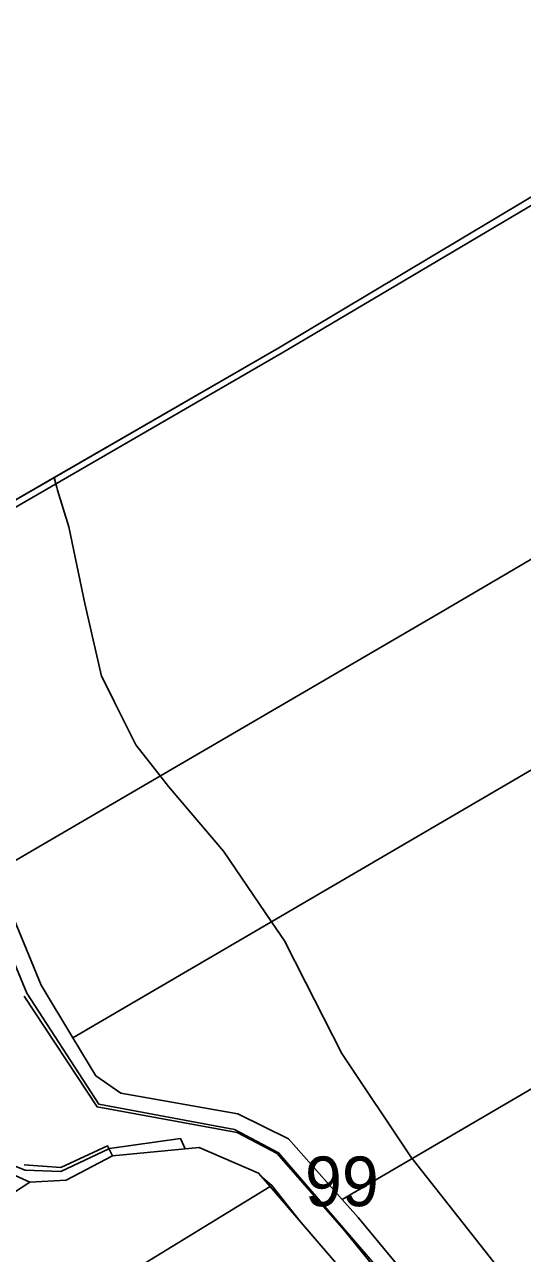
# Model space of a CAD drawing. Extents: x -522079 to -518792, y -1142400 to -1139961.
# Drawn here: x -520688.5 to -520538, y -1140520.9 to -1140149.5 of the extents above; entities that cross this region are included whole.
import ezdxf

# ---------------------------------------------------------------- set-up
doc = ezdxf.new("R2010")
doc.units = 0
for name, color, linetype in [('Hranice parcel', 7, 'Continuous'), ('Parcelní čísla', 7, 'Continuous'), ('Poz předměty', 7, 'Continuous'), ('Vnitřní kresba', 7, 'Continuous'), ('Značky bodu BP', 7, 'Continuous')]:
    doc.layers.add(name, color=color, linetype=linetype)

msp = doc.modelspace()

# ---------------------------------------------------------------- linework, layer by layer
at = {"layer": 'Hranice parcel'}
for points in [[(-520489.41, -1140176.97), (-520610.57, -1140248.68), (-520727.12, -1140316.09), (-520736.79, -1140321.94), (-520738.8, -1140318.04), (-520737.2, -1140317.47), (-520736.37, -1140319.22), (-520728.21, -1140314.51), (-520611.62, -1140247.2), (-520491.09, -1140175.17)], [(-520560.63, -1140549.81), (-520611.7, -1140490.5), (-520625.05, -1140483.49), (-520666, -1140475.86), (-520687.78, -1140442.24), (-520709.46, -1140390.03), (-520724.04, -1140346.68), (-520736.79, -1140321.94), (-520727.12, -1140316.09), (-520729.96, -1140323.84), (-520719.64, -1140344.89), (-520704.93, -1140387.92), (-520697.54, -1140405.82), (-520683.48, -1140439.85), (-520673.87, -1140455.8), (-520666.98, -1140467.24), (-520659.41, -1140472.47), (-520623.97, -1140478.75), (-520608.7, -1140486.32), (-520592.52, -1140504.62), (-520587.65, -1140510.13), (-520562.49, -1140540.48)]]:
    msp.add_lwpolyline(points, dxfattribs=at)
at = {"layer": 'Parcelní čísla'}
for points in [[(-520697.54, -1140405.82), (-520704.93, -1140387.92), (-520719.64, -1140344.89), (-520729.96, -1140323.84), (-520727.12, -1140316.09), (-520610.57, -1140248.68), (-520489.41, -1140176.97), (-520443.64, -1140149.48), (-520437.53, -1140151.12), (-520407.86, -1140236.34), (-520563.45, -1140327.62)], [(-520407.86, -1140236.34), (-520389.24, -1140289.48), (-520535.21, -1140374.77), (-520673.87, -1140455.8), (-520683.48, -1140439.85), (-520697.54, -1140405.82), (-520563.45, -1140327.62)], [(-520592.52, -1140504.62), (-520608.7, -1140486.32), (-520623.97, -1140478.75), (-520659.41, -1140472.47), (-520666.98, -1140467.24), (-520673.87, -1140455.8), (-520535.21, -1140374.77), (-520389.24, -1140289.48), (-520361.23, -1140369.4)], [(-520361.23, -1140369.4), (-520345.47, -1140414.38), (-520469.06, -1140486.19), (-520562.49, -1140540.48), (-520587.65, -1140510.13), (-520592.52, -1140504.62)]]:
    msp.add_lwpolyline(points, close=True, dxfattribs=at)
at = {"layer": 'Poz předměty'}
for points in [[(-520732.54, -1140476.21), (-520724, -1140470.78), (-520714.97, -1140487.48), (-520699.14, -1140493.81), (-520686.89, -1140499.45), (-520708.82, -1140513.67)], [(-520686.89, -1140499.45), (-520675.92, -1140498.77), (-520661.91, -1140491.42), (-520635.69, -1140488.94), (-520617.72, -1140496.63), (-520614.24, -1140500.69), (-520688.32, -1140546.05), (-520708.82, -1140513.67)], [(-520688.32, -1140546.05), (-520614.24, -1140500.69), (-520587.68, -1140531.64), (-520567.56, -1140556.74), (-520562.84, -1140560.36), (-520646.64, -1140611.87)]]:
    msp.add_lwpolyline(points, close=True, dxfattribs=at)
at = {"layer": 'Vnitřní kresba'}
for points in [[(-520709.46, -1140390.03), (-520687.78, -1140442.24), (-520666, -1140475.86), (-520625.05, -1140483.49), (-520611.7, -1140490.5), (-520560.63, -1140549.81)], [(-520688.63, -1140494.17), (-520677.55, -1140494.96), (-520663.43, -1140488.4), (-520661.91, -1140491.42), (-520675.92, -1140498.77), (-520686.89, -1140499.45), (-520699.14, -1140493.81)], [(-520587.68, -1140531.64), (-520614.24, -1140500.69), (-520617.72, -1140496.63), (-520635.69, -1140488.94), (-520661.91, -1140491.42), (-520663.43, -1140488.4), (-520677.55, -1140494.96), (-520688.63, -1140494.17)]]:
    msp.add_lwpolyline(points, dxfattribs=at)
at = {"layer": 'Značky bodu BP'}
for points in [[(-520542.49, -1140528.86), (-520571.02, -1140492.64), (-520571.34, -1140492.23), (-520571.5, -1140492.02), (-520592.55, -1140460.53), (-520603.54, -1140438.95), (-520609.92, -1140426.44), (-520613.83, -1140420.71), (-520628.38, -1140399.39), (-520645.01, -1140379.75), (-520647.47, -1140376.62), (-520654.86, -1140367.24), (-520661.31, -1140354.3), (-520663.36, -1140350.18), (-520665.2, -1140346.48), (-520670.25, -1140324.52), (-520675.06, -1140301.35), (-520678.51, -1140290.17), (-520678.74, -1140289.42), (-520679.03, -1140288.27), (-520679.51, -1140286.39), (-520611.62, -1140247.2), (-520491.09, -1140175.17)], [(-520728.21, -1140314.51), (-520679.51, -1140286.39), (-520679.03, -1140288.27), (-520678.74, -1140289.42), (-520678.51, -1140290.17), (-520675.06, -1140301.35), (-520670.25, -1140324.52), (-520665.2, -1140346.48), (-520663.36, -1140350.18), (-520661.31, -1140354.3), (-520654.86, -1140367.24), (-520647.47, -1140376.62), (-520645.01, -1140379.75), (-520628.38, -1140399.39), (-520613.83, -1140420.71), (-520609.92, -1140426.44), (-520603.54, -1140438.95), (-520592.55, -1140460.53), (-520571.5, -1140492.02), (-520571.34, -1140492.23), (-520571.02, -1140492.64), (-520542.49, -1140528.86)], [(-520562.29, -1140550.47), (-520591.73, -1140514.02), (-520612.12, -1140490.78), (-520624.22, -1140484.36), (-520666.58, -1140476.66), (-520688.6, -1140443.21)], [(-520688.6, -1140443.21), (-520666.58, -1140476.66), (-520624.22, -1140484.36), (-520612.12, -1140490.78), (-520591.73, -1140514.02), (-520562.29, -1140550.47)], [(-520706.32, -1140488.67), (-520688.28, -1140495.8), (-520677.52, -1140496.19), (-520662.98, -1140489.3), (-520662.78, -1140489.2), (-520641.39, -1140486.23), (-520639.91, -1140489.34), (-520635.69, -1140488.94), (-520617.72, -1140496.63), (-520616.5, -1140498.05), (-520613.7, -1140500.4), (-520605.08, -1140511.36), (-520587.68, -1140531.64)], [(-520587.68, -1140531.64), (-520605.08, -1140511.36), (-520613.7, -1140500.4), (-520616.5, -1140498.05), (-520617.72, -1140496.63), (-520635.69, -1140488.94), (-520639.91, -1140489.34), (-520641.39, -1140486.23), (-520662.78, -1140489.2), (-520662.98, -1140489.3), (-520677.52, -1140496.19), (-520688.28, -1140495.8), (-520706.32, -1140488.67)]]:
    msp.add_lwpolyline(points, dxfattribs=at)

# ---------------------------------------------------------------- texts
msp.add_text('99', height=15, rotation=0, dxfattribs=at).set_placement((-520603.71, -1140506.66))

doc.saveas('drawing.dxf')
